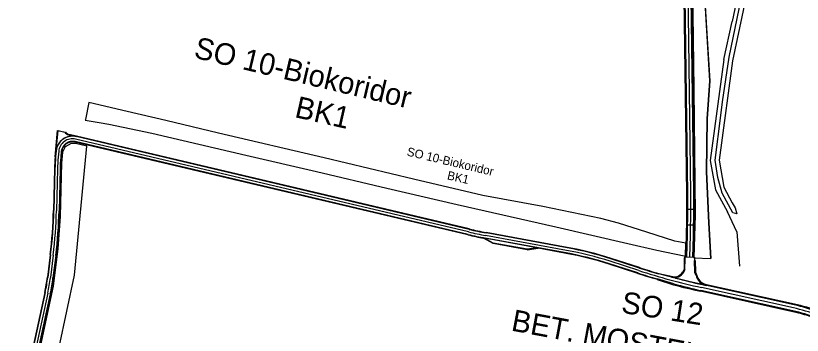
# Model space of a CAD drawing. Extents: x -551750 to -547457, y -1150683 to -1148508.
# Drawn here: x -551264.3 to -550808.7, y -1149548.6 to -1149363.6 of the extents above; entities that cross this region are included whole.
import ezdxf

# ---------------------------------------------------------------- set-up
doc = ezdxf.new("R2010")
doc.units = 0
for name, color, linetype in [('u_BK1_popis', 7, 'Continuous'), ('u_BK1_srafa', 7, 'Continuous'), ('u_IP17', 7, 'Continuous'), ('u_IP17_srafa', 7, 'Continuous'), ('u_ořez_na_hlavu', 7, 'Continuous'), ('u_popis_5000', 7, 'Continuous'), ('u_rekonstrukce mostu', 7, 'Continuous'), ('u_rekonstrukce_mostu_povrch', 7, 'Continuous'), ('u_VC8_cesta', 7, 'Continuous'), ('u_VC8_osa', 7, 'Continuous'), ('u_VC8_srafa', 7, 'Continuous'), ('u_VC9_cesta', 7, 'Continuous'), ('u_VC9_osa', 7, 'Continuous'), ('u_VC9_srafa', 7, 'Continuous'), ('Vrstva 1', 7, 'Continuous')]:
    doc.layers.add(name, color=color, linetype=linetype)

msp = doc.modelspace()

# ---------------------------------------------------------------- linework, layer by layer
at = {"layer": 'u_BK1_srafa'}
for points in [[(-551224.19, -1149424), (-551215.94, -1149425.43), (-551210.44, -1149426.38), (-551185.57, -1149431.58), (-551130.94, -1149444.34), (-551090.18, -1149453.85), (-551049.43, -1149463.37), (-551008.68, -1149472.88), (-550951.47, -1149485.83), (-550909.81, -1149495.47), (-550892.92, -1149499.37), (-550877.18, -1149502.51), (-550876.36, -1149502.71), (-550876.11, -1149495.19), (-550882.45, -1149494.1), (-550898.81, -1149488.89), (-550915.18, -1149483.67), (-550925.29, -1149480.92), (-550958.89, -1149474.08), (-550993.75, -1149467.58), (-551033.93, -1149458.12), (-551085.67, -1149445.94), (-551146.87, -1149431.53), (-551177.47, -1149424.32), (-551199.77, -1149419.07), (-551222.07, -1149413.82), (-551223.98, -1149423.66)], [(-551223.06, -1149439.18), (-551229.67, -1149437.61), (-551232.31, -1149437.58), (-551235.7, -1149439.56), (-551237.2, -1149442.6), (-551237.8, -1149449.03), (-551238.37, -1149472.07), (-551238.56, -1149479.75), (-551239.91, -1149498.42), (-551242.6, -1149520.09), (-551251.79, -1149562.4), (-551260.98, -1149604.71), (-551256.04, -1149624.07), (-551252.49, -1149617.97), (-551230.38, -1149513.73)]]:
    msp.add_lwpolyline(points, close=True, dxfattribs=at)
at = {"layer": 'u_IP17'}
for points in [[(-550875.79, -1149066.52), (-550875.6, -1149089.61), (-550875.41, -1149112.7), (-550874.83, -1149156.2), (-550874.24, -1149199.69), (-550873.8, -1149233.1), (-550872.03, -1149369.71), (-550871.14, -1149442.44), (-550870.69, -1149478.8), (-550871.4, -1149503.74), (-550861.58, -1149504.17)], [(-550869.33, -1149071.89), (-550869.63, -1149076.71), (-550868.86, -1149082.19), (-550868.38, -1149103.81), (-550867.64, -1149132.42), (-550867.72, -1149154.91), (-550867.79, -1149177.4), (-550866.27, -1149203.12), (-550866.43, -1149244.28), (-550866.14, -1149252.83), (-550865.28, -1149278.49), (-550865.28, -1149314.97), (-550865.28, -1149351.45), (-550863.68, -1149377.01), (-550862.16, -1149401.25), (-550863.82, -1149423.34), (-550863.95, -1149438.69), (-550864.07, -1149454.04), (-550862.79, -1149483.43), (-550861.58, -1149504.17)]]:
    msp.add_lwpolyline(points, dxfattribs=at)
at = {"layer": 'u_IP17_srafa'}
msp.add_lwpolyline([(-550872.48, -1149333.35), (-550871.59, -1149406.07), (-550870.69, -1149478.8), (-550871.05, -1149491.27), (-550871.4, -1149503.74), (-550861.58, -1149504.17), (-550862.79, -1149483.43), (-550864.07, -1149454.04), (-550863.82, -1149423.34), (-550862.16, -1149401.25), (-550865.2, -1149352.77)], dxfattribs=at)
at = {"layer": 'u_ořez_na_hlavu'}
msp.add_lwpolyline([(-550837.59, -1149334.93), (-550849.19, -1149389.74), (-550852.33, -1149414.3), (-550853.05, -1149418.49), (-550856.91, -1149447.23), (-550854.2, -1149462.79), (-550849.21, -1149471.84), (-550847.54, -1149474.86), (-550846.65, -1149478.27), (-550848.95, -1149477.76), (-550855.05, -1149466.23), (-550857.63, -1149457.26), (-550859.07, -1149447.26), (-550855.89, -1149421.37), (-550854.9, -1149413.47), (-550850.98, -1149387.55), (-550839.63, -1149332.43)], dxfattribs=at)
at = {"layer": 'u_rekonstrukce mostu'}
for points in [[(-550876.48, -1149503.85), (-550877.06, -1149503.8), (-550877.19, -1149510.51), (-550877.86, -1149511.8), (-550877.46, -1149512.12), (-550876.7, -1149510.67)], [(-550871.12, -1149505.25), (-550870.67, -1149505.25), (-550870.53, -1149512.08), (-550869.7, -1149513.88), (-550870.22, -1149514.05), (-550870.91, -1149512.22)]]:
    msp.add_lwpolyline(points, close=True, dxfattribs=at)
at = {"layer": 'u_rekonstrukce_mostu_povrch'}
msp.add_line((-550869.7, -1149513.88), (-550869.48, -1149514.61), dxfattribs=at)
msp.add_lwpolyline([(-550884.25, -1149514.96), (-550883.07, -1149515.15), (-550882.03, -1149515.13), (-550881.18, -1149514.97), (-550880.18, -1149514.62), (-550879.42, -1149514.19), (-550878.74, -1149513.68), (-550878.13, -1149513.07), (-550877.74, -1149512.56), (-550877.52, -1149512.22), (-550877.46, -1149512.12), (-550876.7, -1149510.67), (-550876.48, -1149503.85), (-550876.48, -1149503.14), (-550871.14, -1149503.3), (-550871.12, -1149505.25), (-550870.91, -1149512.22), (-550870.22, -1149514.05), (-550869.94, -1149514.8), (-550869.65, -1149515.46), (-550868.79, -1149516.84), (-550867.98, -1149517.75), (-550867.24, -1149518.38), (-550866.53, -1149518.85), (-550865.67, -1149519.29), (-550864.92, -1149519.57), (-550864.18, -1149519.77), (-550866.76, -1149519.2), (-550874.47, -1149517.42), (-550882.15, -1149515.48), (-550882.15, -1149515.48)], close=True, dxfattribs=at)
for points in [[(-550876.7, -1149510.67), (-550877.46, -1149512.12), (-550877.37, -1149511.95)], [(-550870.91, -1149512.22), (-550870.22, -1149514.05), (-550869.94, -1149514.78)]]:
    msp.add_lwpolyline(points, dxfattribs=at)
for centre, radius, start, end in [((-550882.69, -1149509.16), 6, 254.9533, 332.3393), ((-550882.69, -1149509.22), 5.5, 254.9533, 331.8277), ((-550862.46, -1149511.96), 8, 200.6589, 257.5409), ((-550862.46, -1149511.96), 7.5, 200.6589, 257.5409)]:
    msp.add_arc(centre, radius, start, end, dxfattribs=at)
at = {"layer": 'u_VC8_cesta'}
for p, q in [((-550875.04, -1149466.64), (-550880.22, -1149067.49)), ((-550871.54, -1149466.59), (-550876.72, -1149067.44)), ((-550875.54, -1149466.64), (-550879.71, -1149145.78)), ((-550871.04, -1149466.59), (-550875.21, -1149145.72)), ((-550876.13, -1149503.15), (-550875.75, -1149490.9)), ((-550875.63, -1149503.17), (-550875.26, -1149490.91)), ((-550872.13, -1149503.27), (-550871.76, -1149491.02)), ((-550871.63, -1149503.29), (-550871.26, -1149491.03))]:
    msp.add_line(p, q, dxfattribs=at)
for radius in [557.75, 558.25, 561.75, 562.25]:
    msp.add_arc((-551433.25, -1149473.88), radius, 358.2517, 0.7434, dxfattribs=at)
at = {"layer": 'u_VC8_osa'}
for points in [[(-550873.29, -1149466.61), (-550878.47, -1149067.47)], [(-550873.88, -1149503.22), (-550873.51, -1149490.96)]]:
    msp.add_lwpolyline(points, dxfattribs=at)
msp.add_arc((-551433.25, -1149473.88), 560, 358.2517, 0.7434, dxfattribs=at)
at = {"layer": 'u_VC8_srafa'}
msp.add_lwpolyline([(-550875.5, -1149475.79), (-550875.6, -1149484.65), (-550871.1, -1149484.73), (-550871, -1149475.8)], close=True, dxfattribs=at)
at = {"layer": 'u_VC9_cesta'}
for p, q in [((-551241.48, -1149445.34), (-551240.05, -1149429.98)), ((-551240.06, -1149430.02), (-551235.52, -1149431.09)), ((-551229.22, -1149433.34), (-551233.51, -1149432.32)), ((-551002.38, -1149490.45), (-551230.02, -1149436.74)), ((-551002.32, -1149490.2), (-551229.96, -1149436.5)), ((-551001.63, -1149487.28), (-551229.27, -1149433.58)), ((-551001.57, -1149487.04), (-551229.22, -1149433.34)), ((-551241.15, -1149441.79), (-551241.48, -1149445.34)), ((-551240.9, -1149441.82), (-551241.23, -1149445.37)), ((-551237.92, -1149442.09), (-551238.25, -1149445.64)), ((-551237.67, -1149442.12), (-551238, -1149445.67)), ((-551241.89, -1149452.26), (-551242.48, -1149476.4)), ((-551241.64, -1149452.27), (-551242.23, -1149476.41)), ((-551238.64, -1149452.34), (-551239.23, -1149476.48)), ((-551238.39, -1149452.35), (-551238.98, -1149476.49)), ((-550987.67, -1149495.18), (-550993.21, -1149492.13)), ((-550944.9, -1149497.94), (-550991.87, -1149489.33)), ((-550944.86, -1149497.7), (-550991.82, -1149489.08)), ((-550987.75, -1149495.42), (-550993.29, -1149492.37)), ((-550945.45, -1149500.89), (-550992.41, -1149492.28)), ((-550968, -1149499.04), (-550987.75, -1149495.42)), ((-550967.99, -1149498.79), (-550987.67, -1149495.18)), ((-550968, -1149499.04), (-550961.74, -1149498.16)), ((-550967.99, -1149498.79), (-550961.73, -1149497.91)), ((-550945.49, -1149501.14), (-550961.74, -1149498.16)), ((-551244.37, -1149501.91), (-551246, -1149515)), ((-551244.13, -1149501.94), (-551245.75, -1149515.03)), ((-551241.15, -1149502.31), (-551242.78, -1149515.4)), ((-551240.9, -1149502.34), (-551242.53, -1149515.44)), ((-550902.98, -1149509.65), (-550919.5, -1149504.33)), ((-550902.9, -1149509.42), (-550919.42, -1149504.1)), ((-550903.97, -1149512.75), (-550920.5, -1149507.43)), ((-550903.9, -1149512.51), (-550920.42, -1149507.19)), ((-550882.15, -1149515.48), (-550891.85, -1149513.06)), ((-550891.79, -1149512.82), (-550883.66, -1149514.63)), ((-550892.74, -1149516.19), (-550883.24, -1149519.33)), ((-550883.1, -1149518.85), (-550892.67, -1149515.94)), ((-550813.31, -1149531.01), (-550866.76, -1149519.2)), ((-550813.2, -1149530.53), (-550864.08, -1149519.29)), ((-551247.51, -1149523.82), (-551264.34, -1149601.01)), ((-551247.26, -1149523.87), (-551264.09, -1149601.07)), ((-550814.17, -1149534.92), (-550867.62, -1149523.11)), ((-550814.07, -1149534.43), (-550867.51, -1149522.62)), ((-551244.33, -1149524.51), (-551261.16, -1149601.71)), ((-551244.09, -1149524.56), (-551260.92, -1149601.76))]:
    msp.add_line(p, q, dxfattribs=at)
for points in [[(-551241.23, -1149445.37), (-551240.9, -1149441.82), (-551239.81, -1149430.07)], [(-551229.27, -1149433.58), (-551233.57, -1149432.57)]]:
    msp.add_lwpolyline(points, dxfattribs=at)
for centre, radius, start, end in [((-551232.65, -1149428.67), 4, 215.4769, 256.7262), ((-551232.65, -1149428.67), 3.75, 220.0464, 256.7262), ((-551231.46, -1149442.83), 9.5, 76.7262, 174.6884), ((-551231.46, -1149442.83), 6.5, 76.7262, 174.6884), ((-551231.46, -1149442.83), 6.25, 76.7262, 174.6884), ((-551140.17, -1149454.76), 101.75, 174.6884, 178.5931), ((-551140.17, -1149454.76), 101.5, 174.6884, 178.5931), ((-551140.17, -1149454.76), 98.5, 174.6884, 178.5931), ((-551140.17, -1149454.76), 98.25, 174.6884, 178.5931), ((-551500.65, -1149470.06), 258.25, 352.9169, 358.5931), ((-551500.65, -1149470.06), 258.5, 352.9169, 358.5931), ((-551500.65, -1149470.06), 261.5, 352.9169, 358.5931), ((-551500.65, -1149470.06), 261.75, 352.9169, 358.5931), ((-550956.05, -1149294.09), 198.5, 256.7262, 259.606), ((-550956.05, -1149294.09), 198.25, 256.7262, 259.606), ((-550956.05, -1149294.09), 201.75, 256.7262, 259.3639), ((-550956.05, -1149294.09), 201.5, 256.7262, 259.606), ((-550981.26, -1149696.14), 198.25, 72.1518, 79.606), ((-550981.26, -1149696.14), 198.5, 72.1518, 79.606), ((-550981.26, -1149696.14), 201.5, 72.1518, 79.606), ((-550981.26, -1149696.14), 201.75, 72.1518, 79.606), ((-550780.84, -1149130.33), 398.5, 252.1518, 253.8249), ((-550780.84, -1149130.33), 398.25, 252.1518, 253.824), ((-550780.84, -1149130.33), 401.75, 252.1518, 253.8274), ((-550780.84, -1149130.33), 401.5, 252.1518, 253.8274), ((-551343.5, -1149502.89), 98.25, 347.7012, 352.9169), ((-551343.5, -1149502.89), 98.5, 347.7012, 352.9169), ((-551343.5, -1149502.89), 101.5, 347.7012, 352.9169), ((-551343.5, -1149502.89), 101.75, 347.7012, 352.9169), ((-550780.84, -1149130.33), 402.25, 255.2523, 257.5409), ((-550780.84, -1149130.33), 401.75, 255.2536, 257.5409), ((-550780.84, -1149130.33), 398.25, 255.2627, 257.5409), ((-550835.26, -1149630.37), 101.75, 61.1359, 77.5409), ((-550835.26, -1149630.37), 102.25, 61.1359, 77.5409), ((-550835.26, -1149630.37), 97.75, 61.1359, 77.5409), ((-550835.26, -1149630.37), 98.25, 61.1359, 77.5409)]:
    msp.add_arc(centre, radius, start, end, dxfattribs=at)
at = {"layer": 'u_VC9_osa'}
msp.add_line((-551239.42, -1149442.09), (-551239.42, -1149442.09), dxfattribs=at)
for points in [[(-551001.98, -1149488.74), (-551229.62, -1149435.04)], [(-551239.41, -1149441.95), (-551239.74, -1149445.51)], [(-551240.14, -1149452.31), (-551240.73, -1149476.45)], [(-550945.18, -1149499.42), (-550992.14, -1149490.8)], [(-551242.64, -1149502.12), (-551244.26, -1149515.22)], [(-550903.44, -1149511.08), (-550919.96, -1149505.76)], [(-550813.69, -1149532.72), (-550867.14, -1149520.91)], [(-551245.8, -1149524.19), (-551262.63, -1149601.39)]]:
    msp.add_lwpolyline(points, dxfattribs=at)
for centre, radius, start, end in [((-551231.46, -1149442.83), 8, 76.7262, 174.6884), ((-551140.17, -1149454.76), 100, 174.6884, 178.5931), ((-551500.65, -1149470.06), 260, 352.9169, 358.5931), ((-550956.05, -1149294.09), 200, 256.7262, 259.606), ((-550981.26, -1149696.14), 200, 72.1518, 79.606), ((-550780.84, -1149130.33), 400, 252.1518, 257.5409), ((-551343.5, -1149502.89), 100, 347.7012, 352.9169), ((-550835.26, -1149630.37), 100, 61.1359, 77.5409)]:
    msp.add_arc(centre, radius, start, end, dxfattribs=at)
at = {"layer": 'u_VC9_srafa'}
for points in [[(-551240.9, -1149441.82), (-551239.81, -1149430.07), (-551235.91, -1149431), (-551235.75, -1149431.2), (-551235.4, -1149431.58), (-551234.99, -1149431.92), (-551234.62, -1149432.15), (-551234.16, -1149432.38), (-551233.73, -1149432.53), (-551233.57, -1149432.57), (-551229.27, -1149433.58), (-551230.26, -1149433.4), (-551230.88, -1149433.34), (-551231.62, -1149433.33), (-551232.19, -1149433.36), (-551232.81, -1149433.42), (-551233.2, -1149433.49), (-551233.93, -1149433.65), (-551235.04, -1149434.03), (-551235.93, -1149434.45), (-551236.51, -1149434.78), (-551237.12, -1149435.2), (-551237.74, -1149435.7), (-551238.14, -1149436.08), (-551238.77, -1149436.77), (-551239.56, -1149437.86), (-551240.24, -1149439.2), (-551240.68, -1149440.57), (-551240.83, -1149441.28)], [(-550993.21, -1149492.13), (-550987.3, -1149493.22), (-550967.63, -1149496.82), (-550961.73, -1149497.91), (-550967.99, -1149498.79), (-550987.67, -1149495.18)]]:
    msp.add_lwpolyline(points, close=True, dxfattribs=at)
at = {"layer": 'Vrstva 1'}
for p, q in [((-550842.46, -1149333.77), (-550849.37, -1149366.94)), ((-550854.12, -1149388.88), (-550849.37, -1149366.94)), ((-550854.12, -1149388.88), (-550861.97, -1149447.33)), ((-550861.97, -1149447.33), (-550858.98, -1149464.47)), ((-550858.98, -1149464.47), (-550852, -1149477.12)), ((-550846.68, -1149488.63), (-550852, -1149477.12)), ((-550846.68, -1149488.63), (-550845.05, -1149508.62))]:
    msp.add_line(p, q, dxfattribs=at)

# ---------------------------------------------------------------- texts
at = {"layer": 'u_BK1_popis'}
for s, rotation, p in [('SO 10-Biokoridor', 346.6634, (-551038.06, -1149444.49)), ('BK1', 347.2922, (-551014.7, -1149458.26))]:
    msp.add_text(s, height=5, rotation=rotation, dxfattribs=at).set_placement(p)
at = {"layer": 'u_popis_5000'}
for s, rotation, p in [('SO 10-Biokoridor', 346.6634, (-551161.66, -1149387.81)), ('BK1', 347.2922, (-551103.25, -1149422.23)), ('SO 12', 351.0383, (-550914.03, -1149535.44)), ('BET. MOSTEK - 11', 349.4385, (-550977.77, -1149545.79))]:
    msp.add_text(s, height=12.5, rotation=rotation, dxfattribs=at).set_placement(p)

doc.saveas('drawing.dxf')
